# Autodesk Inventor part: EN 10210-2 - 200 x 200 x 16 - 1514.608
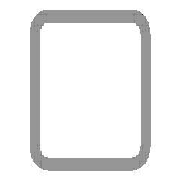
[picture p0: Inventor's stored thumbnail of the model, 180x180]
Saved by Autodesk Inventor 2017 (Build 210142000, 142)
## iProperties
IsCustomPart: 1
Created: 2017-11
Part Number: EN 10210-2 - 200 x 200 x 16 - 1514.608
Material: Steel, Mild
Description: Tube
Document SubType Name: Modeling
Standard: DIN
Designer: iusti
Standard Revision: 2006-07
Standards Organization: DIN
Language: en-US
Size Designation: 200 x 200 x 16
Categories: <MemberInstance><Categories><Category DisplayName="Structural Shapes" InternalName="089c4875-fa83-4c05-b084-43b9cc11f5ed" Mnemonic="GRDR"><CategoryParameter Dis
Stock Number: 200 x 200 x 16
Density: 7.85 g/cm^3
Appearance: Semi-Polished
Mass: 136747 g
Surface Area: 21484.9 cm^2
Volume: 17420 cm^3
_CCFamilyMember: 94
_CCFamilyDisplayName: DIN EN 10210-2 (Square) - Tube — Sizes in parentheses have been withdrawn
_FrameMemberDoc: Frame Member File
_Version: 15.0.0
_GetPNFromCC: 1
G_L: 1514.608 mm
G_W: 200.000 mm
G_H: 200.000 mm
+FBB1E498-9069-44EB-B41A-532C4BDDBF52+CUTDETAIL1: Cut
Author: iusti
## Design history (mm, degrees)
node "Start plane"
node "End plane"
sketch "Sketch"
  geometry: L1 (-100, -76)-(-100, 76); L2 (-76, 100)-(76, 100); L3 (100, 76)-(100, -76); L4 (76, -100)-(-76, -100); L5 (-68, 84)-(68, 84); L6 (84, 68)-(84, -68); L7 (68, -84)-(-68, -84); L8 (-84, -68)-(-84, 68); L9 (0, 146.959)-(0, -146.959) reference; L10 (-146.959, 0)-(146.959, 0) reference; A1 r 24 centre (-76, -76) between (-100, -76) and (-76, -100); A2 r 24 centre (-76, 76) between (-76, 100) and (-100, 76); A3 r 24 centre (76, 76) between (100, 76) and (76, 100); A4 r 24 centre (76, -76) between (76, -100) and (100, -76); A5 r 16 centre (-68, -68) between (-84, -68) and (-68, -84); A6 r 16 centre (-68, 68) between (-68, 84) and (-84, 68); A7 r 16 centre (68, 68) between (84, 68) and (68, 84); A8 r 16 centre (68, -68) between (68, -84) and (84, -68)
  constraints: 16 end point, 16 point on circle, 16 tangent, 8 centre point, 6 equal radius, 4 parallel, 2 perpendicular, 2 other
  dimensions: "d7" = 24 radius of A1 (= G_IR); "d10" = 200 distance between parallel lines of L2 L4 (= G_H); "d11" = 200 distance between parallel lines of L1 L3 (= G_W); "d12" = 16 distance between parallel lines of L3 L6 (= G_T); "d15" = 100 distance between parallel lines of L2 L10 (= 0.5 x d10); "d16" = 100 distance between parallel lines of L9 L3 (= 0.5 x d11); "d19" = 16 radius of A5 (= G_T); "d20" = 16 distance between parallel lines of L4 L7 (= G_T)
extrude "Body" new body sketch "Sketch" stored distance "d3" = 1514.60835 (= G_L); taper "d4" = 0 deg
node "Driven Length"
  sketch "Sketch3"
    geometry: L1 (0, 0)-(10, 0) reference
    constraints: 2 end point, 1 horizontal
  workplane "Work Plane3"
  sketch "Sketch4"
    geometry: L1 (-2, 100)-(12, 100) reference; L2 (-2, 1614.608)-(12, 1614.608) reference
    dimensions: "d18" = 1514.60835 distance between parallel lines of L1 L2 (derived)
workplane "Work Plane4"
split "Split1"
body "Solid1"
other parameters: "G_W" = 200 [user parameter; used in 1 equation term], "G_H" = 200 [user parameter; used in 1 equation term], "G_T" = 16 [user parameter; used in 3 equation terms], "G_IR" = 24 [user parameter; used in 1 equation term], "G_L" = 1514.60835 (= d18) [user parameter; used in 1 equation term], "G_OFFSET_END" = 0 [user parameter; used in 1 equation term], "d14" = 1614.60835 (= G_OFFSET_END + B_L), "B_L" = 1614.60835 [user parameter; used in 1 equation term], "d17" = 90 deg
